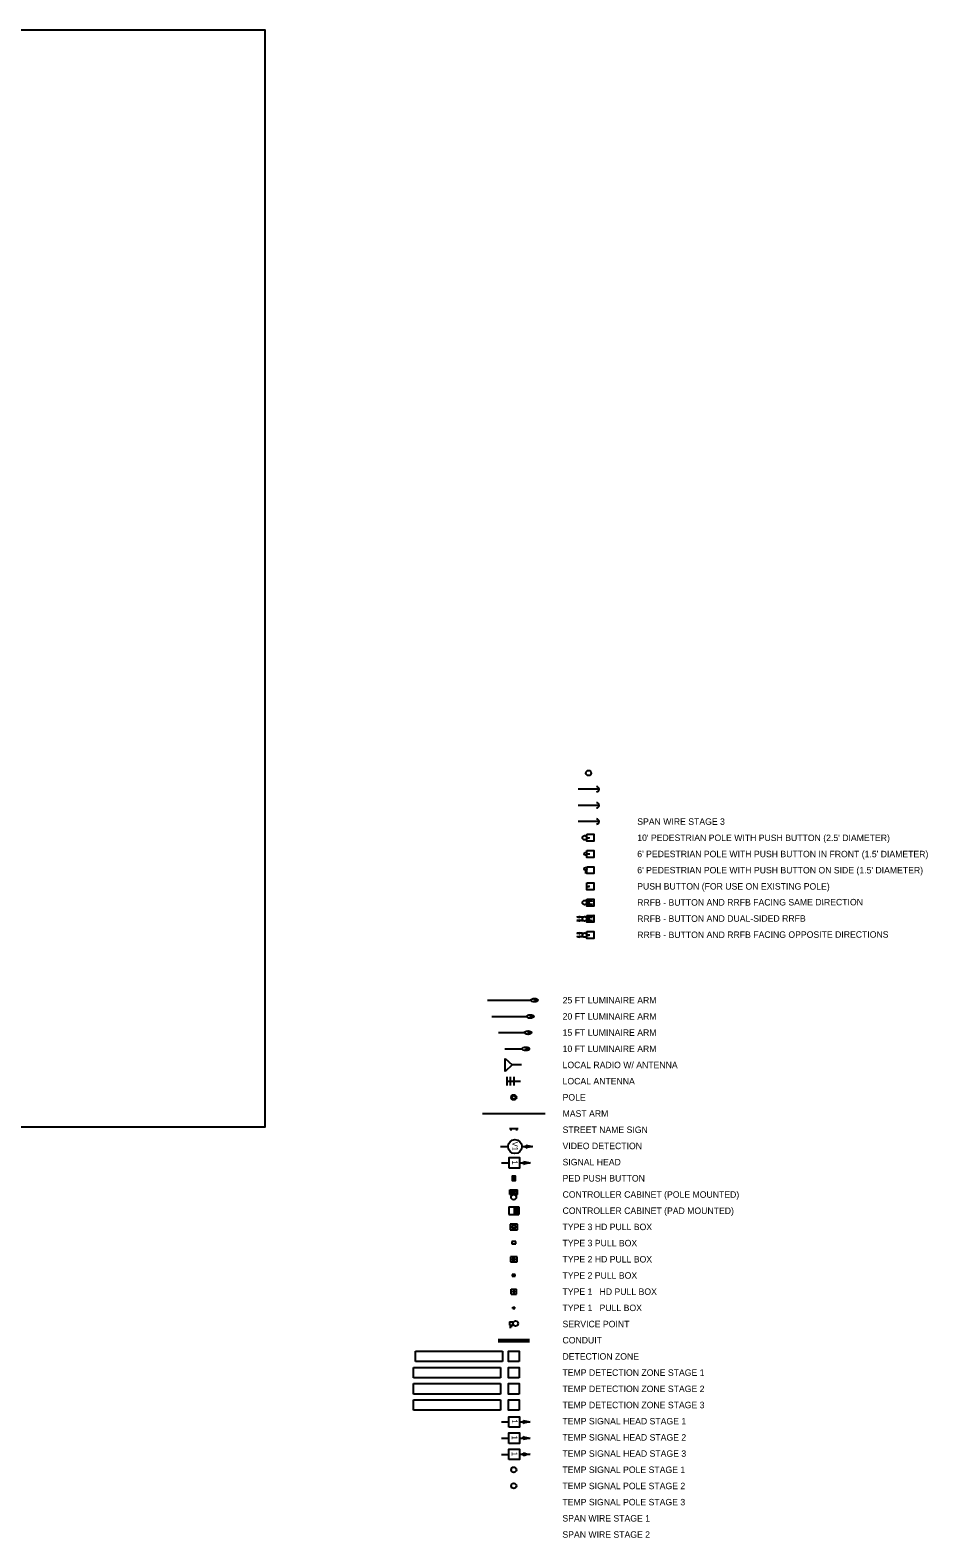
# Model space of a CAD drawing. Extents: x 995332 to 998049, y 1981552 to 1982418.
import ezdxf

# ---------------------------------------------------------------- set-up
doc = ezdxf.new("R2010")
doc.units = 0
for name, color, linetype in [('_CIVIL_CONSTRUCTION', 7, 'Continuous'), ('DSN_DRAIN_Connection-Region', 7, 'Continuous'), ('DSN_DRAIN_Structure', 7, 'Continuous'), ('DSN_DRFT_Const-No-Plot', 7, 'Continuous'), ('DSN_RDWY_Alignment', 7, 'Continuous'), ('DSN_RDWY_Drainage Struct', 7, 'Continuous'), ('DSN_RDWY_Drive', 7, 'Continuous'), ('DSN_RDWY_Pvmt Removal', 7, 'Continuous'), ('EX_CATCH_BASIN_ANNOT', 7, 'Continuous'), ('EX_CONTOUR_ANNOT_MAJOR', 7, 'Continuous'), ('EX_CONTOUR_ANNOT_MINOR', 7, 'Continuous'), ('EX_DROP_INLET_ANNOT', 7, 'Continuous'), ('EX_MANHOLE_ANNOT', 7, 'Continuous'), ('EX_SIGN_ANNOT', 7, 'Continuous'), ('EX_STORM_SEWER_ANNOT', 7, 'Continuous'), ('EX_SURVEY_ANNOT', 7, 'Continuous'), ('EX_TELEPHONE_UTILITIES_ANNOT', 7, 'Continuous'), ('EX_TERRAIN', 7, 'Continuous'), ('EX_TERRAIN_TRIANGLES', 7, 'Continuous'), ('MOD_Const Limits', 7, 'Continuous'), ('S_SIDEWALK', 7, 'Continuous')]:
    doc.layers.add(name, color=color, linetype=linetype)

msp = doc.modelspace()

# ---------------------------------------------------------------- linework, layer by layer
at = {"layer": '_CIVIL_CONSTRUCTION'}
for p, q in [((996506.83, 1981953.99), (996508.15, 1981953.99)), ((996508.15, 1981953.56), (996508.15, 1981954.43)), ((996506.83, 1981944.69), (996508.14, 1981944.69)), ((996508.14, 1981944.26), (996508.14, 1981945.13)), ((996505.64, 1981934.08), (996506.51, 1981934.08)), ((996506.07, 1981935.39), (996506.07, 1981934.08)), ((996506.82, 1981926.09), (996508.14, 1981926.09)), ((996508.14, 1981925.66), (996508.14, 1981926.53)), ((996506.82, 1981916.73), (996508.14, 1981916.73)), ((996508.14, 1981916.3), (996508.14, 1981917.17)), ((996506.84, 1981907.43), (996508.15, 1981907.43)), ((996508.15, 1981907), (996508.15, 1981907.87)), ((996506.85, 1981898.13), (996508.17, 1981898.13)), ((996508.17, 1981897.7), (996508.17, 1981898.57)), ((996467.08, 1981732.11), (996462.75, 1981732.11)), ((996462.75, 1981732.11), (996462.75, 1981728.84)), ((996462.75, 1981728.84), (996467.08, 1981728.84)), ((996463.75, 1981731.11), (996463.75, 1981729.84)), ((996466.08, 1981731.11), (996463.75, 1981731.11)), ((996463.75, 1981729.84), (996466.08, 1981729.84)), ((996466.08, 1981729.84), (996466.08, 1981731.11)), ((996467.08, 1981728.84), (996467.08, 1981732.11)), ((996463.74, 1981721.99), (996463.74, 1981720.72)), ((996466.07, 1981721.99), (996463.74, 1981721.99)), ((996463.74, 1981720.72), (996466.07, 1981720.72)), ((996466.07, 1981720.72), (996466.07, 1981721.99)), ((996466.78, 1981713.33), (996463.03, 1981713.33)), ((996463.03, 1981713.33), (996463.03, 1981710.41)), ((996463.03, 1981710.41), (996466.78, 1981710.41)), ((996464.03, 1981711.41), (996464.03, 1981712.33)), ((996464.03, 1981712.33), (996465.78, 1981712.33)), ((996464.03, 1981712.33), (996464.03, 1981711.41)), ((996465.78, 1981712.33), (996464.03, 1981712.33)), ((996464.03, 1981711.41), (996465.78, 1981711.41)), ((996464.03, 1981711.41), (996465.78, 1981711.41)), ((996465.78, 1981711.41), (996465.78, 1981712.33)), ((996465.78, 1981711.41), (996465.78, 1981712.33)), ((996466.78, 1981710.41), (996466.78, 1981713.33)), ((996464.03, 1981703.04), (996464.03, 1981702.12)), ((996465.78, 1981703.04), (996464.03, 1981703.04)), ((996464.03, 1981702.12), (996465.78, 1981702.12)), ((996465.78, 1981702.12), (996465.78, 1981703.04))]:
    msp.add_line(p, q, dxfattribs=at)
msp.add_lwpolyline([(996464.04, 1981757.06), (996465.79, 1981757.06), (996465.79, 1981759.69), (996464.05, 1981759.69)], close=True, dxfattribs=at)
at = {"layer": 'DSN_DRAIN_Connection-Region'}
for p, q in [((996407.23, 1981649.78), (996457.23, 1981649.78)), ((996407.23, 1981643.78), (996407.23, 1981649.78)), ((996457.23, 1981649.78), (996457.23, 1981643.78)), ((996457.23, 1981643.78), (996407.23, 1981643.78))]:
    msp.add_line(p, q, dxfattribs=at)
msp.add_lwpolyline([(996467.9, 1981643.78), (996461.9, 1981643.78), (996461.9, 1981649.78), (996467.9, 1981649.78)], close=True, dxfattribs=at)
at = {"layer": 'DSN_DRAIN_Structure'}
for p, q in [((996407.22, 1981640.48), (996457.22, 1981640.48)), ((996407.22, 1981634.48), (996407.22, 1981640.48)), ((996457.22, 1981640.48), (996457.22, 1981634.48)), ((996457.22, 1981634.48), (996407.22, 1981634.48))]:
    msp.add_line(p, q, dxfattribs=at)
msp.add_lwpolyline([(996467.9, 1981634.48), (996461.9, 1981634.48), (996461.9, 1981640.48), (996467.9, 1981640.48)], close=True, dxfattribs=at)
at = {"layer": 'DSN_DRFT_Const-No-Plot'}
for p, q in [((996457.25, 1981776.59), (996461.58, 1981776.59)), ((996469.58, 1981776.59), (996475.65, 1981776.59)), ((996457.84, 1981767.21), (996462.19, 1981767.21)), ((996468.25, 1981767.23), (996474.29, 1981767.23))]:
    msp.add_line(p, q, dxfattribs=at)
msp.add_lwpolyline([(996462.19, 1981764.19), (996462.19, 1981770.26), (996468.25, 1981770.26), (996468.25, 1981764.19)], close=True, dxfattribs=at)
msp.add_circle((996465.58, 1981776.59), 4, dxfattribs=at)
for centre, radius, start, end in [((996470.38, 1981776.59), 1.63, 328.15268, 31.84732), ((996480.06, 1981805.73), 29.47, 253.65357, 261.39168), ((996480.06, 1981747.45), 29.47, 98.60832, 106.34643), ((996469.03, 1981767.23), 1.63, 328.15268, 31.84732), ((996478.7, 1981796.37), 29.47, 253.65357, 261.39168), ((996478.7, 1981738.09), 29.47, 98.60832, 106.34643)]:
    msp.add_arc(centre, radius, start, end, dxfattribs=at)
at = {"layer": 'DSN_RDWY_Alignment'}
for p, q in [((996408.39, 1981659.08), (996458.39, 1981659.08)), ((996408.39, 1981653.08), (996408.39, 1981659.08)), ((996458.39, 1981659.08), (996458.39, 1981653.08)), ((996458.39, 1981653.08), (996408.39, 1981653.08))]:
    msp.add_line(p, q, dxfattribs=at)
msp.add_lwpolyline([(996467.91, 1981653.08), (996461.91, 1981653.08), (996461.91, 1981659.08), (996467.91, 1981659.08)], close=True, dxfattribs=at)
at = {"layer": 'DSN_RDWY_Drainage Struct'}
for p, q in [((996462.04, 1981741.94), (996467.78, 1981741.94)), ((996462.04, 1981741.94), (996462.04, 1981737.61)), ((996465.04, 1981741.94), (996465.04, 1981737.61)), ((996467.78, 1981741.94), (996467.78, 1981737.61)), ((996462.04, 1981737.61), (996467.78, 1981737.61)), ((996465.37, 1981741.61), (996465.37, 1981737.94)), ((996465.37, 1981741.61), (996467.45, 1981741.61)), ((996467.45, 1981741.59), (996465.37, 1981737.94)), ((996465.37, 1981737.94), (996467.45, 1981737.94)), ((996467.45, 1981737.94), (996465.38, 1981741.61)), ((996467.45, 1981741.61), (996467.45, 1981737.94))]:
    msp.add_line(p, q, dxfattribs=at)
at = {"layer": 'DSN_RDWY_Drive'}
for p, q in [((996462.4, 1981675.93), (996462.4, 1981673.93)), ((996462.4, 1981675.93), (996464.4, 1981675.93)), ((996462.4, 1981673.93), (996464.4, 1981673.93)), ((996462.4, 1981672.93), (996463.4, 1981672.93)), ((996463.4, 1981673.93), (996463.4, 1981672.93)), ((996464.4, 1981675.93), (996464.4, 1981673.93)), ((996455.83, 1981665.87), (996473.96, 1981665.87)), ((996455.83, 1981664.55), (996473.96, 1981664.55))]:
    msp.add_line(p, q, dxfattribs=at)
msp.add_circle((996465.9, 1981674.93), 1.5, dxfattribs=at)
at = {"layer": 'DSN_RDWY_Pvmt Removal'}
msp.add_lwpolyline([(996464.05, 1981759.69), (996464.04, 1981757.06), (996464.92, 1981757.06), (996464.92, 1981759.69)], close=True, dxfattribs=at)
at = {"layer": 'EX_CATCH_BASIN_ANNOT'}
msp.add_lwpolyline([(995332.18, 1981787.9), (996322.18, 1981787.9), (996322.18, 1982417.9), (995332.18, 1982417.9)], close=True, dxfattribs=at)
at = {"layer": 'EX_CONTOUR_ANNOT_MAJOR'}
msp.add_line((996513.84, 1981981.9), (996501.84, 1981981.9), dxfattribs=at)
msp.add_arc((996512.34, 1981981.9), 1.5, 270, 90, dxfattribs=at)
at = {"layer": 'EX_DROP_INLET_ANNOT'}
for p, q in [((996457.77, 1981609.11), (996462.12, 1981609.11)), ((996468.18, 1981609.13), (996474.22, 1981609.13))]:
    msp.add_line(p, q, dxfattribs=at)
msp.add_lwpolyline([(996462.12, 1981606.09), (996462.12, 1981612.16), (996468.18, 1981612.16), (996468.18, 1981606.09)], close=True, dxfattribs=at)
for centre, radius, start, end in [((996468.96, 1981609.13), 1.63, 328.15268, 31.84732), ((996478.63, 1981638.27), 29.47, 253.65357, 261.39168), ((996478.63, 1981579.99), 29.47, 98.60832, 106.34643)]:
    msp.add_arc(centre, radius, start, end, dxfattribs=at)
at = {"layer": 'EX_MANHOLE_ANNOT'}
msp.add_line((996513.83, 1981963.3), (996501.83, 1981963.3), dxfattribs=at)
msp.add_circle((996507.84, 1981991.19), 1.5, dxfattribs=at)
msp.add_arc((996512.33, 1981963.3), 1.5, 270, 90, dxfattribs=at)
at = {"layer": 'EX_SIGN_ANNOT'}
for p, q in [((996457.77, 1981599.81), (996462.12, 1981599.81)), ((996468.18, 1981599.83), (996474.22, 1981599.83))]:
    msp.add_line(p, q, dxfattribs=at)
msp.add_lwpolyline([(996462.12, 1981596.79), (996462.12, 1981602.86), (996468.18, 1981602.86), (996468.18, 1981596.79)], close=True, dxfattribs=at)
for centre, radius, start, end in [((996468.95, 1981599.83), 1.63, 328.15268, 31.84732), ((996478.63, 1981628.97), 29.47, 253.65357, 261.39168), ((996478.63, 1981570.69), 29.47, 98.60832, 106.34643)]:
    msp.add_arc(centre, radius, start, end, dxfattribs=at)
at = {"layer": 'EX_STORM_SEWER_ANNOT'}
for p, q in [((996457.78, 1981618.41), (996462.12, 1981618.41)), ((996468.19, 1981618.43), (996474.23, 1981618.43))]:
    msp.add_line(p, q, dxfattribs=at)
msp.add_lwpolyline([(996462.12, 1981615.39), (996462.12, 1981621.46), (996468.19, 1981621.46), (996468.19, 1981615.39)], close=True, dxfattribs=at)
for centre, radius, start, end in [((996468.96, 1981618.43), 1.63, 328.15268, 31.84732), ((996478.64, 1981647.57), 29.47, 253.65357, 261.39168), ((996478.64, 1981589.29), 29.47, 98.60832, 106.34643)]:
    msp.add_arc(centre, radius, start, end, dxfattribs=at)
at = {"layer": 'EX_SURVEY_ANNOT'}
for p, q in [((996407.22, 1981631.18), (996457.22, 1981631.18)), ((996407.22, 1981625.18), (996407.22, 1981631.18)), ((996457.22, 1981631.18), (996457.22, 1981625.18)), ((996457.22, 1981625.18), (996407.22, 1981625.18))]:
    msp.add_line(p, q, dxfattribs=at)
msp.add_lwpolyline([(996467.89, 1981625.18), (996461.89, 1981625.18), (996461.89, 1981631.18), (996467.89, 1981631.18)], close=True, dxfattribs=at)
at = {"layer": 'EX_TELEPHONE_UTILITIES_ANNOT'}
msp.add_line((996513.83, 1981972.6), (996501.83, 1981972.6), dxfattribs=at)
msp.add_circle((996464.87, 1981581.68), 1.5, dxfattribs=at)
msp.add_arc((996512.33, 1981972.6), 1.5, 270, 90, dxfattribs=at)
at = {"layer": 'EX_TERRAIN'}
for p, q in [((996467.41, 1981786.78), (996462.41, 1981786.78)), ((996463.41, 1981785.78), (996463.41, 1981786.78)), ((996466.41, 1981786.78), (996466.41, 1981785.78)), ((996467.41, 1981786.78), (996466.41, 1981786.78))]:
    msp.add_line(p, q, dxfattribs=at)
at = {"layer": 'EX_TERRAIN_TRIANGLES'}
for points in [[(996506.83, 1981955.99), (996510.83, 1981955.99), (996510.83, 1981951.99), (996506.83, 1981951.99)], [(996506.83, 1981946.69), (996510.83, 1981946.69), (996510.83, 1981942.69), (996506.83, 1981942.69)], [(996506.82, 1981937.39), (996510.82, 1981937.39), (996510.82, 1981933.39), (996506.82, 1981933.39)], [(996506.82, 1981928.09), (996510.82, 1981928.09), (996510.82, 1981924.09), (996506.82, 1981924.09)], [(996506.81, 1981918.73), (996510.81, 1981918.74), (996510.82, 1981914.74), (996506.82, 1981914.73)], [(996506.83, 1981909.43), (996510.83, 1981909.44), (996510.84, 1981905.44), (996506.84, 1981905.43)], [(996506.85, 1981900.13), (996510.85, 1981900.14), (996510.86, 1981896.14), (996506.86, 1981896.13)]]:
    msp.add_lwpolyline(points, close=True, dxfattribs=at)
at = {"layer": 'MOD_Const Limits'}
for p, q in [((996449.76, 1981860.67), (996474.76, 1981860.67)), ((996452.36, 1981851.37), (996472.36, 1981851.37)), ((996456.06, 1981842.07), (996471.06, 1981842.07)), ((996459.79, 1981832.77), (996469.79, 1981832.77)), ((996459.91, 1981819.76), (996459.91, 1981827.26)), ((996459.91, 1981827.26), (996463.91, 1981823.51)), ((996463.91, 1981823.51), (996459.91, 1981819.76)), ((996469.26, 1981823.51), (996463.91, 1981823.51)), ((996460.83, 1981816.67), (996460.83, 1981811.67)), ((996460.83, 1981814.17), (996468.83, 1981814.17)), ((996462.83, 1981816.67), (996462.83, 1981811.67)), ((996464.83, 1981816.67), (996464.83, 1981811.67)), ((996462.67, 1981749.06), (996462.67, 1981751.8)), ((996462.67, 1981751.8), (996467, 1981751.8)), ((996463, 1981751.47), (996466.67, 1981751.47)), ((996463, 1981749.39), (996463, 1981751.47)), ((996466.67, 1981751.47), (996463, 1981749.39)), ((996463.02, 1981751.47), (996466.67, 1981749.39)), ((996466.67, 1981749.39), (996466.67, 1981751.47)), ((996467, 1981749.06), (996467, 1981751.8)), ((996462.67, 1981749.06), (996467, 1981749.06)), ((996463, 1981749.39), (996466.67, 1981749.39)), ((996463.31, 1981694.64), (996466.5, 1981694.64)), ((996463.31, 1981691.91), (996463.31, 1981694.64)), ((996463.31, 1981691.91), (996466.5, 1981691.91)), ((996464.31, 1981692.91), (996464.31, 1981693.64)), ((996464.31, 1981693.64), (996465.5, 1981693.64)), ((996464.31, 1981692.91), (996465.5, 1981692.91)), ((996465.5, 1981692.91), (996465.5, 1981693.64)), ((996466.5, 1981691.91), (996466.5, 1981694.64)), ((996464.31, 1981683.61), (996464.31, 1981684.34)), ((996464.31, 1981684.34), (996465.5, 1981684.34)), ((996464.31, 1981683.61), (996465.5, 1981683.61)), ((996465.5, 1981683.61), (996465.5, 1981684.34))]:
    msp.add_line(p, q, dxfattribs=at)
msp.add_circle((996464.83, 1981747.56), 1.5, dxfattribs=at)
for centre, major_axis in [((996476.76, 1981860.67), (2, 0)), ((996477.76, 1981860.67), (-1, 0)), ((996474.36, 1981851.37), (2, 0)), ((996475.36, 1981851.37), (-1, 0)), ((996473.06, 1981842.07), (2, 0)), ((996474.06, 1981842.07), (-1, 0)), ((996471.79, 1981832.77), (2, 0)), ((996472.79, 1981832.77), (-1, 0))]:
    msp.add_ellipse(centre, major_axis=major_axis, ratio=0.5, dxfattribs=at)
at = {"layer": 'S_SIDEWALK'}
for p, q in [((996506.82, 1981916.73), (996507.07, 1981916.73)), ((996507.07, 1981915.23), (996507.06, 1981918.23)), ((996507.07, 1981917.73), (996510.09, 1981917.73)), ((996507.07, 1981915.73), (996510.09, 1981915.73)), ((996504.08, 1981908.43), (996501.06, 1981908.42)), ((996504.09, 1981906.43), (996501.07, 1981906.42)), ((996504.08, 1981908.92), (996504.09, 1981905.92)), ((996504.34, 1981907.42), (996504.09, 1981907.42)), ((996506.84, 1981907.43), (996507.09, 1981907.43)), ((996507.09, 1981905.93), (996507.08, 1981908.93)), ((996507.08, 1981908.43), (996510.1, 1981908.43)), ((996507.09, 1981906.43), (996510.11, 1981906.43)), ((996504.1, 1981899.14), (996501.08, 1981899.13)), ((996504.1, 1981899.63), (996504.11, 1981896.63)), ((996504.35, 1981898.13), (996504.1, 1981898.13)), ((996504.1, 1981897.14), (996501.08, 1981897.13)), ((996446.91, 1981795.58), (996482.91, 1981795.58))]:
    msp.add_line(p, q, dxfattribs=at)
for centre, radius in [((996505.58, 1981954), 1.25), ((996506.08, 1981944.69), 0.75), ((996506.07, 1981936.14), 0.75), ((996505.57, 1981916.73), 1.25), ((996505.59, 1981907.43), 1.25), ((996505.6, 1981898.13), 1.25), ((996464.91, 1981804.88), 1.5), ((996464.91, 1981804.88), 1.25), ((996464.91, 1981804.88), 1), ((996464.87, 1981590.98), 1.5)]:
    msp.add_circle(centre, radius, dxfattribs=at)
for centre, radius, start, end in [((996507.45, 1981917.73), 0.814, 328.2824, 31.97704), ((996512.26, 1981932.31), 14.74, 253.78329, 261.52141), ((996512.32, 1981903.17), 14.74, 98.73804, 106.47615), ((996507.46, 1981915.73), 0.814, 328.2824, 31.97704), ((996512.26, 1981930.31), 14.74, 253.78329, 261.52141), ((996512.33, 1981901.17), 14.74, 98.73804, 106.47615), ((996498.82, 1981922.99), 14.74, 278.73804, 286.47615), ((996498.89, 1981893.85), 14.74, 73.78329, 81.52141), ((996498.83, 1981920.99), 14.74, 278.73804, 286.47615), ((996498.89, 1981891.85), 14.74, 73.78329, 81.52141), ((996503.7, 1981908.43), 0.814, 148.2824, 211.97704), ((996503.7, 1981906.43), 0.814, 148.2824, 211.97704), ((996507.47, 1981908.43), 0.814, 328.2824, 31.97704), ((996512.28, 1981923.01), 14.74, 253.78329, 261.52141), ((996512.34, 1981893.87), 14.74, 98.73804, 106.47615), ((996507.47, 1981906.43), 0.814, 328.2824, 31.97704), ((996512.28, 1981921.01), 14.74, 253.78329, 261.52141), ((996512.35, 1981891.87), 14.74, 98.73804, 106.47615), ((996498.84, 1981913.69), 14.74, 278.73804, 286.47615), ((996498.91, 1981884.55), 14.74, 73.78329, 81.52141), ((996503.71, 1981899.14), 0.814, 148.2824, 211.97704), ((996498.85, 1981911.69), 14.74, 278.73804, 286.47615), ((996498.91, 1981882.55), 14.74, 73.78329, 81.52141), ((996503.72, 1981897.14), 0.814, 148.2824, 211.97704)]:
    msp.add_arc(centre, radius, start, end, dxfattribs=at)

# ---------------------------------------------------------------- texts
at = {"layer": 'DSN_DRFT_Const-No-Plot'}
for s, p in [('V1', (996463.99, 1981779.47)), ('1', (996463.84, 1981768.69))]:
    msp.add_text(s, height=3.25, rotation=270, dxfattribs=at).set_placement(p)
at = {"layer": 'EX_CONTOUR_ANNOT_MINOR'}
for s, rotation, p in [('SPAN WIRE STAGE 3', 359.97484, (996535.79, 1981961.44)), ("10' PEDESTRIAN POLE WITH PUSH BUTTON (2.5' DIAMETER)", 359.97484, (996535.79, 1981952.14)), ("6' PEDESTRIAN POLE WITH PUSH BUTTON IN FRONT (1.5' DIAMETER)", 359.97484, (996535.78, 1981942.84)), ("6' PEDESTRIAN POLE WITH PUSH BUTTON ON SIDE (1.5' DIAMETER)", 359.97484, (996535.78, 1981933.54)), ('PUSH BUTTON (FOR USE ON EXISTING POLE)', 359.97484, (996535.77, 1981924.24)), ('RRFB - BUTTON AND RRFB FACING SAME DIRECTION', 0.10457, (996535.78, 1981914.94)), ('RRFB - BUTTON AND DUAL-SIDED RRFB', 0.10457, (996535.79, 1981905.64)), ('RRFB - BUTTON AND RRFB FACING OPPOSITE DIRECTIONS', 0.10457, (996535.81, 1981896.34)), ('25 FT LUMINAIRE ARM', 359.97484, (996492.95, 1981858.83)), ('20 FT LUMINAIRE ARM', 359.97484, (996492.95, 1981849.53)), ('15 FT LUMINAIRE ARM', 359.97484, (996492.94, 1981840.23)), ('10 FT LUMINAIRE ARM', 359.97484, (996492.94, 1981830.93)), ('LOCAL RADIO W/ ANTENNA', 359.97484, (996492.93, 1981821.63)), ('LOCAL ANTENNA', 359.97484, (996492.93, 1981812.33)), ('POLE', 359.97484, (996492.93, 1981803.03)), ('MAST ARM', 359.97484, (996492.92, 1981793.73)), ('STREET NAME SIGN', 359.97484, (996492.92, 1981784.43)), ('VIDEO DETECTION', 359.97484, (996492.91, 1981775.13)), ('SIGNAL HEAD', 359.97484, (996492.91, 1981765.83)), ('PED PUSH BUTTON', 359.97484, (996492.91, 1981756.53)), ('CONTROLLER CABINET (POLE MOUNTED)', 359.97484, (996492.9, 1981747.23)), ('CONTROLLER CABINET (PAD MOUNTED)', 359.97484, (996492.9, 1981737.93)), ('TYPE 3 HD PULL BOX', 359.97484, (996492.89, 1981728.63)), ('TYPE 3 PULL BOX', 359.97484, (996492.89, 1981719.33)), ('TYPE 2 HD PULL BOX', 359.97484, (996492.89, 1981710.03)), ('TYPE 2 PULL BOX', 359.97484, (996492.88, 1981700.73)), ('TYPE 1   HD PULL BOX', 359.97484, (996492.88, 1981691.43)), ('TYPE 1   PULL BOX', 359.97484, (996492.87, 1981682.13)), ('SERVICE POINT', 359.97484, (996492.87, 1981672.83)), ('CONDUIT', 359.97484, (996492.87, 1981663.53)), ('DETECTION ZONE', 359.97484, (996492.86, 1981654.23)), ('TEMP DETECTION ZONE STAGE 1', 359.97484, (996492.86, 1981644.93)), ('TEMP DETECTION ZONE STAGE 2', 359.97484, (996492.85, 1981635.63)), ('TEMP DETECTION ZONE STAGE 3', 359.97484, (996492.85, 1981626.33)), ('TEMP SIGNAL HEAD STAGE 1', 359.97484, (996492.84, 1981617.03)), ('TEMP SIGNAL HEAD STAGE 2', 359.97484, (996492.84, 1981607.73)), ('TEMP SIGNAL HEAD STAGE 3', 359.97484, (996492.84, 1981598.43)), ('TEMP SIGNAL POLE STAGE 1', 359.97484, (996492.83, 1981589.13)), ('TEMP SIGNAL POLE STAGE 2', 359.97484, (996492.83, 1981579.83)), ('TEMP SIGNAL POLE STAGE 3', 359.97484, (996492.82, 1981570.53)), ('SPAN WIRE STAGE 1', 359.97484, (996492.82, 1981561.23)), ('SPAN WIRE STAGE 2', 359.97484, (996492.82, 1981551.93))]:
    msp.add_text(s, height=3.72, rotation=rotation, dxfattribs=at).set_placement(p)
at = {"layer": 'EX_DROP_INLET_ANNOT'}
msp.add_text('1', height=3.25, rotation=270, dxfattribs=at).set_placement((996463.77, 1981610.59))
at = {"layer": 'EX_SIGN_ANNOT'}
msp.add_text('1', height=3.25, rotation=270, dxfattribs=at).set_placement((996463.77, 1981601.29))
at = {"layer": 'EX_STORM_SEWER_ANNOT'}
msp.add_text('1', height=3.25, rotation=270, dxfattribs=at).set_placement((996463.78, 1981619.89))

doc.saveas('drawing.dxf')
